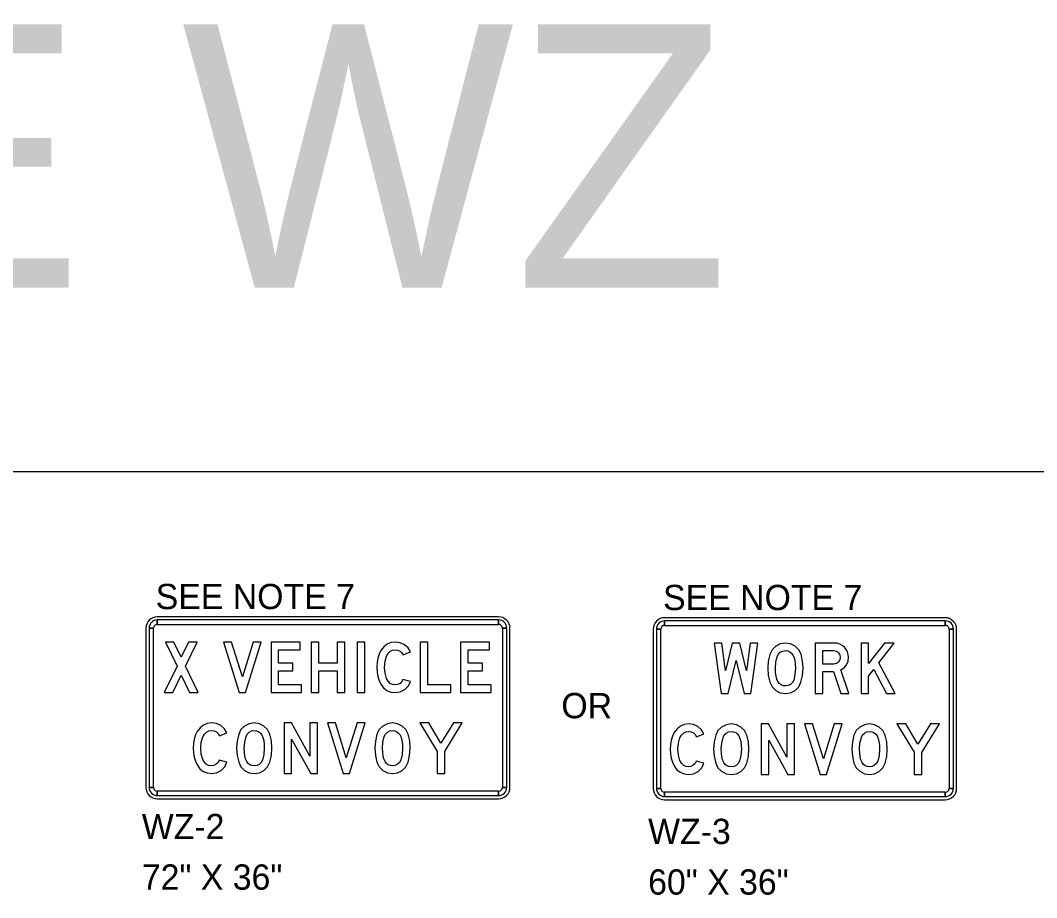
# Model space of a CAD drawing. Extents: x 1806907 to 1812607, y 675071 to 676228.
# Drawn here: x 1811762.5 to 1812003.7, y 676020.1 to 676228.4 of the extents above; entities that cross this region are included whole.
import ezdxf

# ---------------------------------------------------------------- set-up
doc = ezdxf.new("R2010")
doc.units = 0
for name, color, linetype in [('DSN_DRFT_Named-Boundary', 7, 'Continuous'), ('R_No Plot', 7, 'Continuous'), ('Working Level 1', 7, 'Continuous')]:
    doc.layers.add(name, color=color, linetype=linetype)

msp = doc.modelspace()

# ---------------------------------------------------------------- linework, layer by layer
at = {"layer": 'DSN_DRFT_Named-Boundary'}
msp.add_lwpolyline([(1810956.68, 675071.2), (1812606.68, 675071.2), (1812606.68, 676121.2), (1810956.68, 676121.2)], close=True, dxfattribs=at)
at = {"layer": 'Working Level 1'}
for p, q in [((1811876.03, 676086.78), (1811795.03, 676086.78)), ((1811795.03, 676084.98), (1811795.03, 676086.03)), ((1811876.03, 676086.03), (1811876.03, 676084.98)), ((1811982.03, 676086.55), (1811915.43, 676086.55)), ((1811915.43, 676084.75), (1811915.43, 676085.8)), ((1811982.03, 676085.8), (1811982.03, 676084.75)), ((1811792.33, 676084.08), (1811792.33, 676046.29)), ((1811793.08, 676084.08), (1811794.13, 676084.08)), ((1811876.93, 676084.08), (1811877.98, 676084.08)), ((1811878.73, 676046.29), (1811878.73, 676084.08)), ((1811912.73, 676083.85), (1811912.73, 676046.05)), ((1811913.48, 676083.85), (1811914.53, 676083.85)), ((1811982.93, 676083.85), (1811983.98, 676083.85)), ((1811984.73, 676046.05), (1811984.73, 676083.85)), ((1811794.13, 676046.29), (1811793.08, 676046.29)), ((1811795.03, 676044.34), (1811795.03, 676045.39)), ((1811876.03, 676045.39), (1811876.03, 676044.34)), ((1811877.98, 676046.29), (1811876.93, 676046.29)), ((1811914.53, 676046.05), (1811913.48, 676046.05)), ((1811915.43, 676044.1), (1811915.43, 676045.15)), ((1811982.03, 676045.15), (1811982.03, 676044.1)), ((1811983.98, 676046.05), (1811982.93, 676046.05)), ((1811795.03, 676043.59), (1811876.03, 676043.59)), ((1811915.43, 676043.35), (1811982.03, 676043.35))]:
    msp.add_line(p, q, dxfattribs=at)
for points in [[(1811876.03, 676086.03), (1811795.03, 676086.03), (1811795.03, 676084.98), (1811876.03, 676084.98), (1811876.03, 676086.03)], [(1811982.03, 676085.8), (1811915.43, 676085.8), (1811915.43, 676084.75), (1811982.03, 676084.75), (1811982.03, 676085.8)], [(1811793.08, 676084.08), (1811793.08, 676046.29), (1811794.13, 676046.29), (1811794.13, 676084.08), (1811793.08, 676084.08)], [(1811877.98, 676046.29), (1811877.98, 676084.08), (1811876.93, 676084.08), (1811876.93, 676046.29), (1811877.98, 676046.29)], [(1811913.48, 676083.85), (1811913.48, 676046.05), (1811914.53, 676046.05), (1811914.53, 676083.85), (1811913.48, 676083.85)], [(1811983.98, 676046.05), (1811983.98, 676083.85), (1811982.93, 676083.85), (1811982.93, 676046.05), (1811983.98, 676046.05)], [(1811804.72, 676068.79), (1811801.73, 676075.07), (1811804.48, 676080.78), (1811802.47, 676080.78), (1811800.73, 676077.16), (1811799, 676080.78), (1811796.99, 676080.78), (1811799.72, 676075.06), (1811796.71, 676068.79), (1811798.72, 676068.79), (1811800.72, 676072.96), (1811802.72, 676068.79)], [(1811819.71, 676080.78), (1811817.82, 676080.78), (1811815.24, 676072.49), (1811812.67, 676080.78), (1811810.78, 676080.78), (1811814.49, 676068.79), (1811815.98, 676068.79)], [(1811829.28, 676070.6), (1811823.84, 676070.6), (1811823.84, 676073.99), (1811827.23, 676073.99), (1811827.23, 676075.8), (1811823.84, 676075.8), (1811823.84, 676078.97), (1811828.91, 676078.97), (1811828.91, 676080.78), (1811822.03, 676080.78), (1811822.03, 676068.79), (1811829.28, 676068.79)], [(1811839.51, 676068.79), (1811839.51, 676080.78), (1811837.7, 676080.78), (1811837.7, 676075.8), (1811833.4, 676075.8), (1811833.4, 676080.78), (1811831.59, 676080.78), (1811831.59, 676068.79), (1811833.4, 676068.79), (1811833.4, 676073.99), (1811837.7, 676073.99), (1811837.7, 676068.79)], [(1811844.27, 676068.79), (1811844.27, 676080.78), (1811842.46, 676080.78), (1811842.46, 676068.79)], [(1811855.16, 676071.45), (1811853.35, 676071.91), (1811853.08, 676071.38), (1811852.64, 676070.96), (1811852.08, 676070.69), (1811851.45, 676070.6), (1811850.82, 676070.69), (1811850.28, 676070.98), (1811849.82, 676071.46), (1811849.45, 676072.12), (1811849.08, 676073.36), (1811848.96, 676074.78), (1811849.09, 676076.22), (1811849.47, 676077.46), (1811849.85, 676078.12), (1811850.31, 676078.59), (1811850.87, 676078.88), (1811851.51, 676078.97), (1811852.11, 676078.89), (1811852.66, 676078.64), (1811853.11, 676078.25), (1811853.42, 676077.75), (1811855.16, 676078.43), (1811854.57, 676079.39), (1811853.72, 676080.14), (1811852.68, 676080.62), (1811851.54, 676080.78), (1811850.48, 676080.66), (1811849.56, 676080.28), (1811848.77, 676079.66), (1811848.12, 676078.78), (1811847.69, 676077.92), (1811847.39, 676076.96), (1811847.21, 676075.92), (1811847.15, 676074.79), (1811847.21, 676073.66), (1811847.39, 676072.62), (1811847.69, 676071.67), (1811848.11, 676070.81), (1811848.75, 676069.92), (1811849.53, 676069.29), (1811850.43, 676068.91), (1811851.48, 676068.79), (1811852.7, 676068.97), (1811853.8, 676069.52), (1811854.65, 676070.38)], [(1811864.72, 676068.79), (1811864.72, 676070.6), (1811859.27, 676070.6), (1811859.27, 676080.78), (1811857.46, 676080.78), (1811857.46, 676068.79)], [(1811874.28, 676070.6), (1811868.84, 676070.6), (1811868.84, 676073.99), (1811872.23, 676073.99), (1811872.23, 676075.8), (1811868.84, 676075.8), (1811868.84, 676078.97), (1811873.91, 676078.97), (1811873.91, 676080.78), (1811867.03, 676080.78), (1811867.03, 676068.79), (1811874.28, 676068.79)], [(1811937.59, 676080.55), (1811935.76, 676080.55), (1811934.84, 676073.98), (1811933.25, 676080.55), (1811931.5, 676080.55), (1811929.92, 676073.97), (1811929, 676080.55), (1811927.17, 676080.55), (1811928.85, 676068.55), (1811930.48, 676068.55), (1811932.38, 676076.44), (1811934.28, 676068.55), (1811935.91, 676068.55)], [(1811948.29, 676074.56), (1811948.17, 676076.27), (1811947.8, 676077.87), (1811947.26, 676078.95), (1811946.4, 676079.81), (1811945.32, 676080.36), (1811944.1, 676080.55), (1811942.88, 676080.36), (1811941.8, 676079.81), (1811940.94, 676078.95), (1811940.4, 676077.86), (1811940.04, 676076.26), (1811939.91, 676074.56), (1811940.04, 676072.86), (1811940.4, 676071.25), (1811940.94, 676070.16), (1811941.8, 676069.3), (1811942.88, 676068.74), (1811944.1, 676068.55), (1811945.31, 676068.73), (1811946.4, 676069.29), (1811947.25, 676070.14), (1811947.79, 676071.23), (1811948.16, 676072.84)], [(1811959.17, 676068.55), (1811957.28, 676074.15), (1811958.02, 676074.67), (1811958.59, 676075.4), (1811958.96, 676076.25), (1811959.09, 676077.18), (1811959.02, 676077.85), (1811958.84, 676078.47), (1811958.53, 676079.04), (1811958.09, 676079.56), (1811957.56, 676079.99), (1811956.99, 676080.3), (1811956.36, 676080.49), (1811955.69, 676080.55), (1811951.16, 676080.55), (1811951.16, 676068.55), (1811952.98, 676068.55), (1811952.98, 676073.76), (1811955.49, 676073.76), (1811957.26, 676068.55)], [(1811970.17, 676068.55), (1811966.27, 676075.86), (1811969.88, 676080.55), (1811967.59, 676080.55), (1811963.85, 676075.69), (1811963.85, 676080.55), (1811962.04, 676080.55), (1811962.04, 676068.55), (1811963.85, 676068.55), (1811963.85, 676072.72), (1811965.06, 676074.28), (1811968.12, 676068.55)], [(1811946.48, 676074.55), (1811946.37, 676073.09), (1811946.06, 676071.74), (1811945.77, 676071.17), (1811945.32, 676070.73), (1811944.75, 676070.45), (1811944.11, 676070.36), (1811943.55, 676070.42), (1811943.06, 676070.62), (1811942.65, 676070.95), (1811942.32, 676071.41), (1811942.06, 676072), (1811941.87, 676072.72), (1811941.76, 676073.57), (1811941.73, 676074.55), (1811941.83, 676076), (1811942.15, 676077.35), (1811942.44, 676077.92), (1811942.89, 676078.36), (1811943.46, 676078.64), (1811944.11, 676078.74), (1811944.66, 676078.67), (1811945.14, 676078.48), (1811945.55, 676078.15), (1811945.89, 676077.69), (1811946.14, 676077.1), (1811946.33, 676076.38), (1811946.44, 676075.53)], [(1811952.98, 676075.57), (1811952.98, 676078.74), (1811955.61, 676078.74), (1811956.19, 676078.62), (1811956.68, 676078.27), (1811957.01, 676077.76), (1811957.12, 676077.15), (1811957.01, 676076.54), (1811956.68, 676076.03), (1811956.19, 676075.68), (1811955.61, 676075.57)], [(1811811.57, 676052.25), (1811809.75, 676052.71), (1811809.48, 676052.18), (1811809.04, 676051.76), (1811808.48, 676051.49), (1811807.86, 676051.4), (1811807.23, 676051.49), (1811806.68, 676051.78), (1811806.23, 676052.26), (1811805.86, 676052.92), (1811805.49, 676054.16), (1811805.37, 676055.58), (1811805.49, 676057.02), (1811805.87, 676058.26), (1811806.25, 676058.92), (1811806.72, 676059.39), (1811807.27, 676059.68), (1811807.92, 676059.77), (1811808.51, 676059.69), (1811809.06, 676059.44), (1811809.52, 676059.05), (1811809.83, 676058.55), (1811811.57, 676059.23), (1811810.98, 676060.19), (1811810.12, 676060.94), (1811809.08, 676061.42), (1811807.94, 676061.58), (1811806.89, 676061.46), (1811805.97, 676061.08), (1811805.18, 676060.46), (1811804.52, 676059.58), (1811804.1, 676058.72), (1811803.8, 676057.76), (1811803.62, 676056.72), (1811803.56, 676055.59), (1811803.61, 676054.46), (1811803.79, 676053.42), (1811804.09, 676052.47), (1811804.51, 676051.61), (1811805.15, 676050.72), (1811805.93, 676050.09), (1811806.84, 676049.71), (1811807.88, 676049.59), (1811809.1, 676049.77), (1811810.2, 676050.32), (1811811.06, 676051.18)], [(1811822.25, 676055.59), (1811822.12, 676057.3), (1811821.76, 676058.91), (1811821.22, 676059.99), (1811820.36, 676060.85), (1811819.27, 676061.4), (1811818.05, 676061.58), (1811816.83, 676061.4), (1811815.75, 676060.85), (1811814.9, 676059.99), (1811814.36, 676058.9), (1811813.99, 676057.29), (1811813.87, 676055.59), (1811813.99, 676053.89), (1811814.36, 676052.28), (1811814.9, 676051.19), (1811815.75, 676050.33), (1811816.83, 676049.77), (1811818.05, 676049.59), (1811819.27, 676049.77), (1811820.35, 676050.32), (1811821.21, 676051.18), (1811821.75, 676052.26), (1811822.12, 676053.87)], [(1811833.04, 676049.59), (1811833.04, 676061.58), (1811831.23, 676061.58), (1811831.23, 676053.7), (1811826.86, 676061.58), (1811825.12, 676061.58), (1811825.12, 676049.59), (1811826.93, 676049.59), (1811826.93, 676057.73), (1811831.45, 676049.59)], [(1811844.37, 676061.58), (1811842.47, 676061.58), (1811839.9, 676053.29), (1811837.33, 676061.58), (1811835.43, 676061.58), (1811839.15, 676049.59), (1811840.64, 676049.59)], [(1811855.06, 676055.59), (1811854.94, 676057.3), (1811854.57, 676058.91), (1811854.03, 676059.99), (1811853.17, 676060.85), (1811852.08, 676061.4), (1811850.86, 676061.58), (1811849.64, 676061.4), (1811848.56, 676060.85), (1811847.71, 676059.99), (1811847.17, 676058.9), (1811846.8, 676057.29), (1811846.68, 676055.59), (1811846.8, 676053.89), (1811847.17, 676052.28), (1811847.71, 676051.19), (1811848.56, 676050.33), (1811849.64, 676049.77), (1811850.86, 676049.59), (1811852.08, 676049.77), (1811853.16, 676050.32), (1811854.02, 676051.18), (1811854.56, 676052.26), (1811854.93, 676053.87)], [(1811867.43, 676061.58), (1811865.3, 676061.58), (1811862.36, 676056.79), (1811859.48, 676061.58), (1811857.37, 676061.58), (1811861.45, 676054.84), (1811861.45, 676049.59), (1811863.26, 676049.59), (1811863.26, 676054.79)], [(1811924.77, 676052.01), (1811922.95, 676052.47), (1811922.68, 676051.95), (1811922.24, 676051.53), (1811921.68, 676051.25), (1811921.06, 676051.16), (1811920.43, 676051.26), (1811919.89, 676051.54), (1811919.43, 676052.02), (1811919.06, 676052.69), (1811918.69, 676053.92), (1811918.57, 676055.35), (1811918.69, 676056.79), (1811919.08, 676058.02), (1811919.45, 676058.68), (1811919.92, 676059.16), (1811920.47, 676059.44), (1811921.12, 676059.54), (1811921.71, 676059.45), (1811922.26, 676059.21), (1811922.72, 676058.81), (1811923.03, 676058.31), (1811924.77, 676058.99), (1811924.18, 676059.96), (1811923.32, 676060.71), (1811922.28, 676061.19), (1811921.14, 676061.35), (1811920.09, 676061.22), (1811919.17, 676060.85), (1811918.38, 676060.22), (1811917.72, 676059.35), (1811917.3, 676058.48), (1811917, 676057.53), (1811916.82, 676056.49), (1811916.76, 676055.36), (1811916.81, 676054.23), (1811917, 676053.19), (1811917.29, 676052.24), (1811917.71, 676051.37), (1811918.35, 676050.49), (1811919.13, 676049.86), (1811920.04, 676049.47), (1811921.08, 676049.35), (1811922.31, 676049.53), (1811923.4, 676050.09), (1811924.26, 676050.94)], [(1811935.45, 676055.36), (1811935.32, 676057.07), (1811934.96, 676058.67), (1811934.42, 676059.75), (1811933.56, 676060.61), (1811932.47, 676061.16), (1811931.25, 676061.35), (1811930.03, 676061.16), (1811928.95, 676060.61), (1811928.1, 676059.75), (1811927.56, 676058.66), (1811927.19, 676057.06), (1811927.07, 676055.36), (1811927.19, 676053.66), (1811927.56, 676052.05), (1811928.1, 676050.96), (1811928.95, 676050.1), (1811930.03, 676049.54), (1811931.25, 676049.35), (1811932.47, 676049.53), (1811933.55, 676050.09), (1811934.41, 676050.94), (1811934.95, 676052.03), (1811935.32, 676053.64)], [(1811946.24, 676049.35), (1811946.24, 676061.35), (1811944.43, 676061.35), (1811944.43, 676053.46), (1811940.06, 676061.35), (1811938.32, 676061.35), (1811938.32, 676049.35), (1811940.13, 676049.35), (1811940.13, 676057.49), (1811944.65, 676049.35)], [(1811957.57, 676061.35), (1811955.67, 676061.35), (1811953.1, 676053.06), (1811950.53, 676061.35), (1811948.63, 676061.35), (1811952.35, 676049.35), (1811953.84, 676049.35)], [(1811968.26, 676055.36), (1811968.14, 676057.07), (1811967.77, 676058.67), (1811967.23, 676059.75), (1811966.37, 676060.61), (1811965.28, 676061.16), (1811964.06, 676061.35), (1811962.84, 676061.16), (1811961.76, 676060.61), (1811960.91, 676059.75), (1811960.37, 676058.66), (1811960, 676057.06), (1811959.88, 676055.36), (1811960, 676053.66), (1811960.37, 676052.05), (1811960.91, 676050.96), (1811961.76, 676050.1), (1811962.84, 676049.54), (1811964.06, 676049.35), (1811965.28, 676049.53), (1811966.36, 676050.09), (1811967.22, 676050.94), (1811967.76, 676052.03), (1811968.13, 676053.64)], [(1811980.63, 676061.35), (1811978.5, 676061.35), (1811975.56, 676056.56), (1811972.68, 676061.35), (1811970.57, 676061.35), (1811974.65, 676054.61), (1811974.65, 676049.35), (1811976.46, 676049.35), (1811976.46, 676054.56)], [(1811820.44, 676055.58), (1811820.33, 676054.13), (1811820.01, 676052.77), (1811819.72, 676052.21), (1811819.27, 676051.77), (1811818.71, 676051.49), (1811818.07, 676051.4), (1811817.5, 676051.46), (1811817.02, 676051.66), (1811816.61, 676051.98), (1811816.28, 676052.44), (1811816.01, 676053.03), (1811815.83, 676053.75), (1811815.72, 676054.6), (1811815.68, 676055.58), (1811815.79, 676057.04), (1811816.11, 676058.39), (1811816.39, 676058.95), (1811816.84, 676059.4), (1811817.41, 676059.68), (1811818.07, 676059.77), (1811818.62, 676059.71), (1811819.1, 676059.51), (1811819.51, 676059.18), (1811819.84, 676058.73), (1811820.1, 676058.14), (1811820.29, 676057.42), (1811820.4, 676056.56)], [(1811853.25, 676055.58), (1811853.14, 676054.13), (1811852.82, 676052.77), (1811852.53, 676052.21), (1811852.08, 676051.77), (1811851.52, 676051.49), (1811850.88, 676051.4), (1811850.32, 676051.46), (1811849.83, 676051.66), (1811849.42, 676051.98), (1811849.09, 676052.44), (1811848.83, 676053.03), (1811848.64, 676053.75), (1811848.53, 676054.6), (1811848.49, 676055.58), (1811848.6, 676057.04), (1811848.92, 676058.39), (1811849.2, 676058.95), (1811849.65, 676059.4), (1811850.22, 676059.68), (1811850.88, 676059.77), (1811851.43, 676059.71), (1811851.91, 676059.51), (1811852.32, 676059.18), (1811852.65, 676058.73), (1811852.91, 676058.14), (1811853.1, 676057.42), (1811853.21, 676056.56)], [(1811933.64, 676055.35), (1811933.53, 676053.89), (1811933.21, 676052.54), (1811932.92, 676051.97), (1811932.47, 676051.53), (1811931.91, 676051.25), (1811931.27, 676051.16), (1811930.7, 676051.23), (1811930.22, 676051.42), (1811929.81, 676051.75), (1811929.48, 676052.21), (1811929.21, 676052.8), (1811929.03, 676053.52), (1811928.92, 676054.37), (1811928.88, 676055.35), (1811928.99, 676056.8), (1811929.31, 676058.15), (1811929.59, 676058.72), (1811930.04, 676059.16), (1811930.61, 676059.44), (1811931.27, 676059.54), (1811931.82, 676059.47), (1811932.3, 676059.28), (1811932.71, 676058.95), (1811933.04, 676058.49), (1811933.3, 676057.9), (1811933.49, 676057.18), (1811933.6, 676056.33)], [(1811966.45, 676055.35), (1811966.34, 676053.89), (1811966.02, 676052.54), (1811965.73, 676051.97), (1811965.28, 676051.53), (1811964.72, 676051.25), (1811964.08, 676051.16), (1811963.52, 676051.23), (1811963.03, 676051.42), (1811962.62, 676051.75), (1811962.29, 676052.21), (1811962.03, 676052.8), (1811961.84, 676053.52), (1811961.73, 676054.37), (1811961.69, 676055.35), (1811961.8, 676056.8), (1811962.12, 676058.15), (1811962.4, 676058.72), (1811962.85, 676059.16), (1811963.42, 676059.44), (1811964.08, 676059.54), (1811964.63, 676059.47), (1811965.11, 676059.28), (1811965.52, 676058.95), (1811965.85, 676058.49), (1811966.11, 676057.9), (1811966.3, 676057.18), (1811966.41, 676056.33)], [(1811795.03, 676044.34), (1811876.03, 676044.34), (1811876.03, 676045.39), (1811795.03, 676045.39), (1811795.03, 676044.34)], [(1811915.43, 676044.1), (1811982.03, 676044.1), (1811982.03, 676045.15), (1811915.43, 676045.15), (1811915.43, 676044.1)]]:
    msp.add_lwpolyline(points, close=True, dxfattribs=at)
for centre, radius, start, end in [((1811795.03, 676084.08), 2.7, 90.0002, 179.9998), ((1811795.03, 676084.08), 1.95, 90.0002, 179.9998), ((1811795.03, 676084.08), 0.9, 90.0002, 179.9998), ((1811876.03, 676084.08), 2.7, 0, 90.0002), ((1811876.03, 676084.08), 1.95, 0, 90.0002), ((1811876.03, 676084.08), 0.9, 0, 90.0002), ((1811915.43, 676083.85), 2.7, 90.0002, 179.9998), ((1811915.43, 676083.85), 1.95, 90.0002, 179.9998), ((1811982.03, 676083.85), 2.7, 0, 90.0002), ((1811982.03, 676083.85), 1.95, 0, 90.0002), ((1811915.43, 676083.85), 0.9, 90.0002, 179.9998), ((1811982.03, 676083.85), 0.9, 0, 90.0002), ((1811795.03, 676046.29), 2.7, 179.9998, 270.0001), ((1811795.03, 676046.29), 1.95, 179.9998, 270.0001), ((1811795.03, 676046.29), 0.9, 179.9998, 270.0001), ((1811876.03, 676046.29), 2.7, 270.0001, 0.0003), ((1811876.03, 676046.29), 1.95, 270.0001, 0.0003), ((1811876.03, 676046.29), 0.9, 270.0001, 0.0003), ((1811915.43, 676046.05), 2.7, 179.9998, 270.0001), ((1811915.43, 676046.05), 1.95, 179.9998, 270.0001), ((1811915.43, 676046.05), 0.9, 179.9998, 270.0001), ((1811982.03, 676046.05), 2.7, 270.0001, 0.0003), ((1811982.03, 676046.05), 1.95, 270.0001, 0.0003), ((1811982.03, 676046.05), 0.9, 270.0001, 0.0003)]:
    msp.add_arc(centre, radius, start, end, dxfattribs=at)

# ---------------------------------------------------------------- texts
at = {"layer": 'R_No Plot'}
msp.add_text('MOBILE WZ', height=62.502, dxfattribs=at).set_placement((1811461.79, 676164.93))
at = {"layer": 'Working Level 1'}
for p in [(1811794.67, 676088.59), (1811915.07, 676088.36)]:
    msp.add_text('SEE NOTE 7 ', height=6, dxfattribs=at).set_placement(p)
for s, p in [('OR', (1811890.93, 676062.69)), ('WZ-2', (1811791.37, 676034)), ('WZ-3', (1811911.52, 676032.83)), ('72" X 36"', (1811791.37, 676022)), ('60" X 36"', (1811911.52, 676020.83))]:
    msp.add_text(s, height=6, rotation=0, dxfattribs=at).set_placement(p)

doc.saveas('drawing.dxf')
